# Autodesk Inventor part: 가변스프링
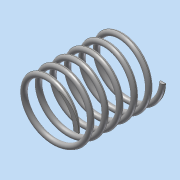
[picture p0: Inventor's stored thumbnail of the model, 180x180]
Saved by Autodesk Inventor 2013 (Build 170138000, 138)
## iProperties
Created: 2018-06
Part Number: 가변스프링
Material: 강철, 연강
Document SubType Name: Modeling
Designer: Administrator
Mass: 83.1659 g
Surface Area: 106.47 cm^2
Volume: 10.5809 cm^3
Density: 7.86 g/cm^3
Author: Administrator
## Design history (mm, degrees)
sketch "스케치1"
  geometry: L1 (0, 0)-(0, 73.25); L2 (0, 0)-(22.5, 0); L3 (0, 73.25)-(22.5, 73.25); C1 r 2 at (22.5, 0)
  constraints: 6 end point, 1 centre point, 1 coincident, 1 parallel, 1 perpendicular, 1 vertical
  dimensions: "d0" = 73.25 distance of L1.start L1.end (derived); "d1" = 45 diameter of L3.end L1; "d2" = 45 diameter of L2.end L1; "d3" = 4 diameter of C1
feature "코일1" sketch "스케치1" pitch "d4" = 10; turns "d6" = 6; dims "d5" = 73.25 (= d0), "d7" = 0, angle "d8" = 90 deg, angle "d9" = 90 deg, "d10" = 0, "d11" = 0
sketch "스케치2"
  geometry: L1 (-25, 73.25)-(25, 73.25); L2 (25, 73.25)-(25, 0); L3 (25, 0)-(-25, 0); L4 (-25, 0)-(-25, 73.25); 2 further points
  constraints: 8 end point, 2 parallel, 1 coincident, 1 horizontal, 1 midpoint, 1 perpendicular
  dimensions: "d12" = 73.25 distance of L1.end L2.end (derived); "d13" = 50 distance of L1.start L1.end
extrude "돌출1" sketch "스케치2" stored distance "d14" = 50; taper "d15" = 0 deg
node "솔리드1"
